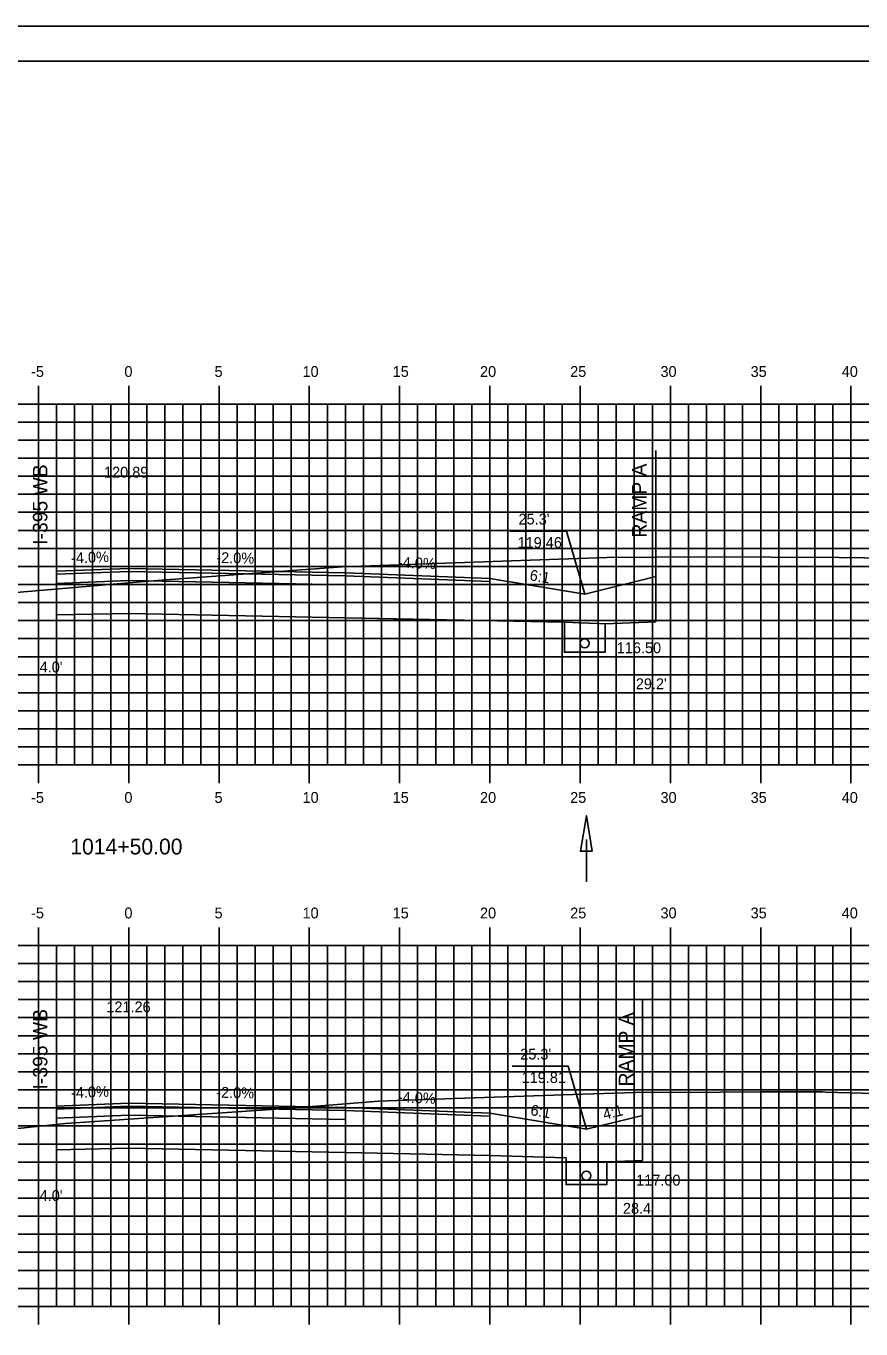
# Model space of a CAD drawing. Extents: x 852847 to 853019, y 365624 to 365734.
# Drawn here: x 852924.6 to 852970.9, y 365661.8 to 365734 of the extents above; entities that cross this region are included whole.
import ezdxf

# ---------------------------------------------------------------- set-up
doc = ezdxf.new("R2010")
doc.units = 0
for name, color, linetype in [('ANNOTATION', 7, 'Continuous'), ('BORDER', 7, 'Continuous'), ('D_Drainage_Ditch_Line', 7, 'Continuous'), ('D_Roadway_Centerline', 7, 'Continuous'), ('D_Roadway_Centerline_Text', 7, 'Continuous'), ('D_Roadway_Edge_Shoulder', 7, 'Continuous'), ('D_Roadway_Edge_TW', 7, 'Continuous'), ('D_Roadway_FinishedGrade', 7, 'Continuous'), ('D_Roadway_Pavement', 7, 'Continuous'), ('D_Roadway_SubGrade', 7, 'Continuous'), ('D_Text_Standard', 7, 'Continuous'), ('Default', 7, 'Continuous'), ('H_V ANNOTATION', 7, 'Continuous'), ('M_Roadway_Centerline', 7, 'Continuous'), ('MAJOR', 7, 'Continuous'), ('MINOR', 7, 'Continuous'), ('PDRAIN', 7, 'Continuous'), ('PLOT BOUNDARY', 7, 'Continuous'), ('S_Roadway_Centerline', 7, 'Continuous')]:
    doc.layers.add(name, color=color, linetype=linetype)

msp = doc.modelspace()

# ---------------------------------------------------------------- linework, layer by layer
at = {"layer": 'ANNOTATION'}
for points in [[(852951.438, 365705.988), (852954.547, 365705.988), (852955.558, 365702.482)], [(852951.531, 365676.345), (852954.64, 365676.345), (852955.651, 365672.84)]]:
    msp.add_lwpolyline(points, dxfattribs=at)
at = {"layer": 'BORDER'}
msp.add_lwpolyline([(852855.305, 365627.027), (853015.305, 365627.027), (853015.305, 365732.027), (852855.305, 365732.027)], close=True, dxfattribs=at)
at = {"layer": 'D_Drainage_Ditch_Line'}
msp.add_line((852955.651, 365688.901), (852955.651, 365686.551), dxfattribs=at)
msp.add_lwpolyline([(852955.979, 365688.245), (852955.323, 365688.245), (852955.651, 365690.213)], close=True, dxfattribs=at)
at = {"layer": 'D_Roadway_Centerline'}
for p, q in [((852959.488, 365703.465), (852959.488, 365700.965)), ((852942.305, 365701.178), (852954.433, 365700.935)), ((852956.683, 365700.853), (852954.433, 365700.935)), ((852956.776, 365671.036), (852954.526, 365671.036))]:
    msp.add_line(p, q, dxfattribs=at)
for points in [[(852926.305, 365703.758), (852930.305, 365703.918), (852930.309, 365703.918), (852942.305, 365703.678), (852942.308, 365703.678), (852950.305, 365703.358)], [(852950.305, 365703.358), (852955.558, 365702.482), (852959.488, 365703.465)], [(852959.488, 365700.965), (852956.683, 365700.853)], [(852926.304, 365674.131), (852930.303, 365674.291), (852930.305, 365674.291), (852942.301, 365674.051), (852942.305, 365674.051), (852950.303, 365673.731), (852950.305, 365673.731)], [(852950.304, 365673.731), (852955.651, 365672.84), (852958.751, 365673.614)], [(852954.526, 365671.253), (852950.304, 365671.391)], [(852958.752, 365671.115), (852956.776, 365671.036)]]:
    msp.add_lwpolyline(points, dxfattribs=at)
at = {"layer": 'D_Roadway_Edge_Shoulder'}
for points in [[(852930.305, 365703.918), (852926.305, 365703.758), (852926.305, 365703.591), (852930.305, 365703.751)], [(852942.305, 365703.678), (852950.305, 365703.358), (852950.305, 365703.191), (852942.305, 365703.511)], [(852930.305, 365674.291), (852926.304, 365674.131), (852926.304, 365673.964), (852930.305, 365674.124)], [(852942.305, 365674.051), (852950.304, 365673.731), (852950.304, 365673.564), (852942.305, 365673.884)]]:
    msp.add_lwpolyline(points, close=True, dxfattribs=at)
at = {"layer": 'D_Roadway_Edge_TW'}
for points in [[(852930.305, 365703.918), (852942.305, 365703.678), (852942.305, 365703.511), (852930.305, 365703.751)], [(852930.305, 365674.291), (852942.305, 365674.051), (852942.305, 365673.884), (852930.305, 365674.124)]]:
    msp.add_lwpolyline(points, close=True, dxfattribs=at)
for points in [[(852942.305, 365703.678), (852942.305, 365703.511)], [(852942.305, 365674.051), (852942.305, 365673.884)]]:
    msp.add_lwpolyline(points, dxfattribs=at)
at = {"layer": 'D_Roadway_FinishedGrade'}
for p, q in [((852926.305, 365703.758), (852926.305, 365703.508)), ((852930.305, 365703.918), (852930.305, 365703.668)), ((852942.308, 365703.678), (852942.308, 365703.428)), ((852950.305, 365703.358), (852950.305, 365703.108)), ((852926.304, 365674.131), (852926.304, 365673.881)), ((852930.305, 365674.291), (852930.305, 365674.041)), ((852942.305, 365674.051), (852942.305, 365673.801)), ((852950.304, 365673.731), (852950.304, 365673.481))]:
    msp.add_line(p, q, dxfattribs=at)
at = {"layer": 'D_Roadway_Pavement'}
for points in [[(852930.305, 365703.751), (852926.305, 365703.591), (852926.305, 365703.091), (852930.305, 365703.251)], [(852930.305, 365703.751), (852942.305, 365703.511), (852942.305, 365703.011), (852930.305, 365703.251)], [(852930.305, 365674.124), (852926.304, 365673.964), (852926.304, 365673.464), (852930.305, 365673.624)], [(852930.305, 365674.124), (852942.305, 365673.884), (852942.305, 365673.384), (852930.305, 365673.624)]]:
    msp.add_lwpolyline(points, close=True, dxfattribs=at)
for points in [[(852942.305, 365703.511), (852942.305, 365703.011)], [(852942.305, 365703.511), (852942.305, 365703.011)], [(852942.305, 365673.884), (852942.305, 365673.384)], [(852942.305, 365673.884), (852942.305, 365673.384)]]:
    msp.add_lwpolyline(points, dxfattribs=at)
at = {"layer": 'D_Roadway_SubGrade'}
for p, q in [((852926.305, 365710.216), (852926.305, 365701.338)), ((852959.488, 365710.446), (852959.488, 365700.965)), ((852926.304, 365680.035), (852926.304, 365671.711)), ((852958.751, 365680.076), (852958.751, 365671.115))]:
    msp.add_line(p, q, dxfattribs=at)
for points in [[(852930.305, 365703.251), (852926.305, 365703.091), (852926.305, 365703.591), (852926.305, 365703.758), (852926.305, 365701.338), (852930.305, 365701.418)], [(852942.305, 365703.011), (852942.305, 365703.511), (852950.305, 365703.191), (852950.305, 365703.358), (852950.305, 365701.018), (852942.305, 365701.178)], [(852930.305, 365703.251), (852942.305, 365703.011), (852942.305, 365701.178), (852930.305, 365701.418)], [(852930.305, 365673.624), (852926.304, 365673.464), (852926.304, 365673.964), (852926.304, 365674.131), (852926.304, 365671.711), (852930.305, 365671.791)], [(852942.305, 365673.384), (852942.305, 365673.884), (852950.304, 365673.564), (852950.304, 365673.731), (852950.304, 365671.391), (852942.305, 365671.551)], [(852930.305, 365673.624), (852942.305, 365673.384), (852942.305, 365671.551), (852930.305, 365671.791)]]:
    msp.add_lwpolyline(points, close=True, dxfattribs=at)
for points in [[(852942.305, 365703.011), (852942.305, 365701.178)], [(852942.305, 365673.384), (852942.305, 365671.551)]]:
    msp.add_lwpolyline(points, dxfattribs=at)
at = {"layer": 'Default'}
msp.add_line((852950.304, 365673.731), (852955.651, 365672.84), dxfattribs=at)
at = {"layer": 'MAJOR'}
for p, q in [((852925.305, 365714.029), (852925.305, 365713.027)), ((852930.305, 365714.029), (852930.305, 365713.027)), ((852935.305, 365714.029), (852935.305, 365713.027)), ((852940.305, 365714.029), (852940.305, 365713.027)), ((852945.305, 365714.029), (852945.305, 365713.027)), ((852950.305, 365714.029), (852950.305, 365713.027)), ((852955.305, 365714.029), (852955.305, 365713.027)), ((852960.305, 365714.029), (852960.305, 365713.027)), ((852965.305, 365714.029), (852965.305, 365713.027)), ((852970.305, 365714.029), (852970.305, 365713.027)), ((852860.305, 365713.027), (853000.305, 365713.027)), ((852860.305, 365713.027), (853000.305, 365713.027)), ((852925.305, 365693.027), (852925.305, 365713.027)), ((852930.305, 365693.027), (852930.305, 365713.027)), ((852935.305, 365693.027), (852935.305, 365713.027)), ((852940.305, 365693.027), (852940.305, 365713.027)), ((852945.305, 365693.027), (852945.305, 365713.027)), ((852950.305, 365693.027), (852950.305, 365713.027)), ((852955.305, 365693.027), (852955.305, 365713.027)), ((852960.305, 365693.027), (852960.305, 365713.027)), ((852965.305, 365693.027), (852965.305, 365713.027)), ((852970.305, 365693.027), (852970.305, 365713.027)), ((852860.305, 365708.027), (853000.305, 365708.027)), ((852860.305, 365703.027), (853000.305, 365703.027)), ((852860.305, 365698.027), (853000.305, 365698.027)), ((852860.305, 365693.027), (853000.305, 365693.027)), ((852860.305, 365693.027), (853000.305, 365693.027)), ((852925.305, 365692.025), (852925.305, 365693.027)), ((852930.305, 365692.025), (852930.305, 365693.027)), ((852935.305, 365692.025), (852935.305, 365693.027)), ((852940.305, 365692.025), (852940.305, 365693.027)), ((852945.305, 365692.025), (852945.305, 365693.027)), ((852950.305, 365692.025), (852950.305, 365693.027)), ((852955.305, 365692.025), (852955.305, 365693.027)), ((852960.305, 365692.025), (852960.305, 365693.027)), ((852965.305, 365692.025), (852965.305, 365693.027)), ((852970.305, 365692.025), (852970.305, 365693.027)), ((852925.305, 365684.029), (852925.305, 365683.027)), ((852930.305, 365684.029), (852930.305, 365683.027)), ((852935.305, 365684.029), (852935.305, 365683.027)), ((852940.305, 365684.029), (852940.305, 365683.027)), ((852945.305, 365684.029), (852945.305, 365683.027)), ((852950.305, 365684.029), (852950.305, 365683.027)), ((852955.305, 365684.029), (852955.305, 365683.027)), ((852960.305, 365684.029), (852960.305, 365683.027)), ((852965.305, 365684.029), (852965.305, 365683.027)), ((852970.305, 365684.029), (852970.305, 365683.027)), ((852860.305, 365683.027), (853000.305, 365683.027)), ((852860.305, 365683.027), (853000.305, 365683.027)), ((852925.305, 365663.027), (852925.305, 365683.027)), ((852930.305, 365663.027), (852930.305, 365683.027)), ((852935.305, 365663.027), (852935.305, 365683.027)), ((852940.305, 365663.027), (852940.305, 365683.027)), ((852945.305, 365663.027), (852945.305, 365683.027)), ((852950.305, 365663.027), (852950.305, 365683.027)), ((852955.305, 365663.027), (852955.305, 365683.027)), ((852960.305, 365663.027), (852960.305, 365683.027)), ((852965.305, 365663.027), (852965.305, 365683.027)), ((852970.305, 365663.027), (852970.305, 365683.027)), ((852860.305, 365678.027), (853000.305, 365678.027)), ((852860.305, 365673.027), (853000.305, 365673.027)), ((852860.305, 365668.027), (853000.305, 365668.027)), ((852860.305, 365663.027), (853000.305, 365663.027)), ((852860.305, 365663.027), (853000.305, 365663.027)), ((852925.305, 365662.025), (852925.305, 365663.027)), ((852930.305, 365662.025), (852930.305, 365663.027)), ((852935.305, 365662.025), (852935.305, 365663.027)), ((852940.305, 365662.025), (852940.305, 365663.027)), ((852945.305, 365662.025), (852945.305, 365663.027)), ((852950.305, 365662.025), (852950.305, 365663.027)), ((852955.305, 365662.025), (852955.305, 365663.027)), ((852960.305, 365662.025), (852960.305, 365663.027)), ((852965.305, 365662.025), (852965.305, 365663.027)), ((852970.305, 365662.025), (852970.305, 365663.027))]:
    msp.add_line(p, q, dxfattribs=at)
at = {"layer": 'MINOR'}
for p, q in [((852926.305, 365693.027), (852926.305, 365713.027)), ((852927.305, 365693.027), (852927.305, 365713.027)), ((852928.305, 365693.027), (852928.305, 365713.027)), ((852929.305, 365693.027), (852929.305, 365713.027)), ((852931.305, 365693.027), (852931.305, 365713.027)), ((852932.305, 365693.027), (852932.305, 365713.027)), ((852933.305, 365693.027), (852933.305, 365713.027)), ((852934.305, 365693.027), (852934.305, 365713.027)), ((852936.305, 365693.027), (852936.305, 365713.027)), ((852937.305, 365693.027), (852937.305, 365713.027)), ((852938.305, 365693.027), (852938.305, 365713.027)), ((852939.305, 365693.027), (852939.305, 365713.027)), ((852941.305, 365693.027), (852941.305, 365713.027)), ((852942.305, 365693.027), (852942.305, 365713.027)), ((852943.305, 365693.027), (852943.305, 365713.027)), ((852944.305, 365693.027), (852944.305, 365713.027)), ((852946.305, 365693.027), (852946.305, 365713.027)), ((852947.305, 365693.027), (852947.305, 365713.027)), ((852948.305, 365693.027), (852948.305, 365713.027)), ((852949.305, 365693.027), (852949.305, 365713.027)), ((852951.305, 365693.027), (852951.305, 365713.027)), ((852952.305, 365693.027), (852952.305, 365713.027)), ((852953.305, 365693.027), (852953.305, 365713.027)), ((852954.305, 365693.027), (852954.305, 365713.027)), ((852956.305, 365693.027), (852956.305, 365713.027)), ((852957.305, 365693.027), (852957.305, 365713.027)), ((852958.305, 365693.027), (852958.305, 365713.027)), ((852959.305, 365693.027), (852959.305, 365713.027)), ((852961.305, 365693.027), (852961.305, 365713.027)), ((852962.305, 365693.027), (852962.305, 365713.027)), ((852963.305, 365693.027), (852963.305, 365713.027)), ((852964.305, 365693.027), (852964.305, 365713.027)), ((852966.305, 365693.027), (852966.305, 365713.027)), ((852967.305, 365693.027), (852967.305, 365713.027)), ((852968.305, 365693.027), (852968.305, 365713.027)), ((852969.305, 365693.027), (852969.305, 365713.027)), ((852860.305, 365712.027), (853000.305, 365712.027)), ((852860.305, 365711.027), (853000.305, 365711.027)), ((852860.305, 365710.027), (853000.305, 365710.027)), ((852860.305, 365709.027), (853000.305, 365709.027)), ((852860.305, 365707.027), (853000.305, 365707.027)), ((852860.305, 365706.027), (853000.305, 365706.027)), ((852860.305, 365705.027), (853000.305, 365705.027)), ((852860.305, 365704.027), (853000.305, 365704.027)), ((852860.305, 365702.027), (853000.305, 365702.027)), ((852860.305, 365701.027), (853000.305, 365701.027)), ((852860.305, 365700.027), (853000.305, 365700.027)), ((852860.305, 365699.027), (853000.305, 365699.027)), ((852860.305, 365697.027), (853000.305, 365697.027)), ((852860.305, 365696.027), (853000.305, 365696.027)), ((852860.305, 365695.027), (853000.305, 365695.027)), ((852860.305, 365694.027), (853000.305, 365694.027)), ((852926.305, 365663.027), (852926.305, 365683.027)), ((852927.305, 365663.027), (852927.305, 365683.027)), ((852928.305, 365663.027), (852928.305, 365683.027)), ((852929.305, 365663.027), (852929.305, 365683.027)), ((852931.305, 365663.027), (852931.305, 365683.027)), ((852932.305, 365663.027), (852932.305, 365683.027)), ((852933.305, 365663.027), (852933.305, 365683.027)), ((852934.305, 365663.027), (852934.305, 365683.027)), ((852936.305, 365663.027), (852936.305, 365683.027)), ((852937.305, 365663.027), (852937.305, 365683.027)), ((852938.305, 365663.027), (852938.305, 365683.027)), ((852939.305, 365663.027), (852939.305, 365683.027)), ((852941.305, 365663.027), (852941.305, 365683.027)), ((852942.305, 365663.027), (852942.305, 365683.027)), ((852943.305, 365663.027), (852943.305, 365683.027)), ((852944.305, 365663.027), (852944.305, 365683.027)), ((852946.305, 365663.027), (852946.305, 365683.027)), ((852947.305, 365663.027), (852947.305, 365683.027)), ((852948.305, 365663.027), (852948.305, 365683.027)), ((852949.305, 365663.027), (852949.305, 365683.027)), ((852951.305, 365663.027), (852951.305, 365683.027)), ((852952.305, 365663.027), (852952.305, 365683.027)), ((852953.305, 365663.027), (852953.305, 365683.027)), ((852954.305, 365663.027), (852954.305, 365683.027)), ((852956.305, 365663.027), (852956.305, 365683.027)), ((852957.305, 365663.027), (852957.305, 365683.027)), ((852958.305, 365663.027), (852958.305, 365683.027)), ((852959.305, 365663.027), (852959.305, 365683.027)), ((852961.305, 365663.027), (852961.305, 365683.027)), ((852962.305, 365663.027), (852962.305, 365683.027)), ((852963.305, 365663.027), (852963.305, 365683.027)), ((852964.305, 365663.027), (852964.305, 365683.027)), ((852966.305, 365663.027), (852966.305, 365683.027)), ((852967.305, 365663.027), (852967.305, 365683.027)), ((852968.305, 365663.027), (852968.305, 365683.027)), ((852969.305, 365663.027), (852969.305, 365683.027)), ((852860.305, 365682.027), (853000.305, 365682.027)), ((852860.305, 365681.027), (853000.305, 365681.027)), ((852860.305, 365680.027), (853000.305, 365680.027)), ((852860.305, 365679.027), (853000.305, 365679.027)), ((852860.305, 365677.027), (853000.305, 365677.027)), ((852860.305, 365676.027), (853000.305, 365676.027)), ((852860.305, 365675.027), (853000.305, 365675.027)), ((852860.305, 365674.027), (853000.305, 365674.027)), ((852860.305, 365672.027), (853000.305, 365672.027)), ((852860.305, 365671.027), (853000.305, 365671.027)), ((852860.305, 365670.027), (853000.305, 365670.027)), ((852860.305, 365669.027), (853000.305, 365669.027)), ((852860.305, 365667.027), (853000.305, 365667.027)), ((852860.305, 365666.027), (853000.305, 365666.027)), ((852860.305, 365665.027), (853000.305, 365665.027)), ((852860.305, 365664.027), (853000.305, 365664.027))]:
    msp.add_line(p, q, dxfattribs=at)
at = {"layer": 'PDRAIN'}
for points in [[(852954.433, 365700.935), (852954.433, 365699.271), (852956.683, 365699.271), (852956.683, 365700.853)], [(852954.526, 365671.253), (852954.526, 365669.774), (852956.776, 365669.774), (852956.776, 365671.036)]]:
    msp.add_lwpolyline(points, dxfattribs=at)
for centre in [(852955.558, 365699.771), (852955.651, 365670.274)]:
    msp.add_circle(centre, 0.25, dxfattribs=at)
at = {"layer": 'PLOT BOUNDARY'}
msp.add_lwpolyline([(852847.212, 365623.968), (853017.212, 365623.968), (853017.212, 365733.968), (852847.212, 365733.968)], close=True, dxfattribs=at)
at = {"layer": 'S_Roadway_Centerline'}
for points in [[(852923.423, 365702.524), (852930.953, 365703.18), (852932.624, 365703.299), (852942.124, 365704.007), (852950.47, 365704.305), (852952.545, 365704.368), (852956.79, 365704.525), (852962.095, 365704.551), (852969.654, 365704.522), (852971.063, 365704.511), (852986.326, 365703.852), (852987.344, 365703.811), (852987.79, 365703.787), (852988, 365703.722), (852990.182, 365703.23), (853000.305, 365701.246)], [(852918.469, 365672.292), (852926.799, 365673.154), (852937.922, 365673.922), (852939.535, 365674.03), (852939.906, 365674.06), (852940.215, 365674.084), (852941.397, 365674.18), (852944.138, 365674.402), (852946.198, 365674.474), (852955.457, 365674.78), (852958.961, 365674.891), (852961.401, 365674.889), (852963.083, 365674.897), (852965.393, 365674.916), (852968.724, 365674.924), (852968.893, 365674.908), (852974.97, 365674.735), (852977.127, 365674.63), (852986.317, 365674.095), (852986.928, 365674.078), (852994.385, 365672.658), (852997.766, 365672.075), (853000.305, 365671.445)]]:
    msp.add_lwpolyline(points, dxfattribs=at)

# ---------------------------------------------------------------- texts
at = {"layer": 'ANNOTATION'}
for s, height, rotation, p in [('I-395 WB', 0.8, 90, (852925.798, 365705.225)), ('RAMP A', 0.8, 90, (852958.981, 365705.627)), ("25.3' ", 0.6, 360, (852951.891, 365706.351)), ('119.46', 0.6, 360, (852951.84, 365705.051)), ('-4.0%', 0.6, 2.2904, (852927.122, 365704.191)), ('-2.0%', 0.6, 358.85423, (852935.15, 365704.221)), ('-4.0%', 0.6, 357.7093, (852945.202, 365703.963)), ('6:1', 0.6, 350.53768, (852952.478, 365703.266)), ('I-395 WB', 0.8, 90, (852925.798, 365675.049)), ('RAMP A', 0.8, 90, (852958.244, 365675.217)), ("25.3' ", 0.6, 360, (852951.984, 365676.708)), ('119.81', 0.6, 360, (852952.062, 365675.408)), ('-4.0%', 0.6, 2.29042, (852927.12, 365674.564)), ('-2.0%', 0.6, 358.85423, (852935.146, 365674.594)), ('-4.0%', 0.6, 357.70931, (852945.2, 365674.336)), ('6:1', 0.6, 350.53768, (852952.524, 365673.631)), ('4:1', 0.6, 14.02518, (852956.647, 365673.364))]:
    msp.add_text(s, height=height, rotation=rotation, dxfattribs=at).set_placement(p)
at = {"layer": 'D_Roadway_Centerline'}
for s, p in [('C', (852930.3, 365703.918)), ('L', (852930.305, 365703.91)), ('C', (852930.299, 365674.291)), ('L', (852930.305, 365674.283))]:
    msp.add_text(s, height=0.0146, dxfattribs=at).set_placement(p)
at = {"layer": 'D_Roadway_Centerline_Text'}
for s, p in [('120.89', (852928.935, 365708.95)), ('121.26', (852929.064, 365679.323))]:
    msp.add_text(s, height=0.6, dxfattribs=at).set_placement(p)
at = {"layer": 'D_Text_Standard'}
for s, p in [('116.50', (852957.333, 365699.221)), ("4.0'", (852925.371, 365698.156)), ("29.2'", (852958.388, 365697.226)), ('117.00', (852958.408, 365669.724)), ("4.0'", (852925.371, 365668.872)), ("28.4'", (852957.673, 365668.162))]:
    msp.add_text(s, height=0.6, dxfattribs=at).set_placement(p)
at = {"layer": 'H_V ANNOTATION'}
for s, height, p in [('-5', 0.6, (852924.896, 365714.527)), ('0', 0.6, (852930.064, 365714.527)), ('5', 0.6, (852935.056, 365714.527)), ('10', 0.6, (852939.93, 365714.527)), ('15', 0.6, (852944.922, 365714.527)), ('20', 0.6, (852949.759, 365714.527)), ('25', 0.6, (852954.751, 365714.527)), ('30', 0.6, (852959.754, 365714.527)), ('35', 0.6, (852964.746, 365714.527)), ('40', 0.6, (852969.791, 365714.527)), ('-5', 0.6, (852924.896, 365690.927)), ('0', 0.6, (852930.064, 365690.927)), ('5', 0.6, (852935.056, 365690.927)), ('10', 0.6, (852939.93, 365690.927)), ('15', 0.6, (852944.922, 365690.927)), ('20', 0.6, (852949.759, 365690.927)), ('25', 0.6, (852954.751, 365690.927)), ('30', 0.6, (852959.754, 365690.927)), ('35', 0.6, (852964.746, 365690.927)), ('40', 0.6, (852969.791, 365690.927)), ('1014+50.00', 0.875, (852927.067, 365688.07)), ('-5', 0.6, (852924.896, 365684.527)), ('0', 0.6, (852930.064, 365684.527)), ('5', 0.6, (852935.056, 365684.527)), ('10', 0.6, (852939.93, 365684.527)), ('15', 0.6, (852944.922, 365684.527)), ('20', 0.6, (852949.759, 365684.527)), ('25', 0.6, (852954.751, 365684.527)), ('30', 0.6, (852959.754, 365684.527)), ('35', 0.6, (852964.746, 365684.527)), ('40', 0.6, (852969.791, 365684.527))]:
    msp.add_text(s, height=height, dxfattribs=at).set_placement(p)
at = {"layer": 'M_Roadway_Centerline'}
for s, p in [('C', (852956.785, 365704.525)), ('L', (852956.79, 365704.518)), ('C', (852958.955, 365674.891)), ('L', (852958.961, 365674.883)), ('C', (852968.719, 365674.924)), ('L', (852968.724, 365674.917))]:
    msp.add_text(s, height=0.0146, dxfattribs=at).set_placement(p)

doc.saveas('drawing.dxf')
